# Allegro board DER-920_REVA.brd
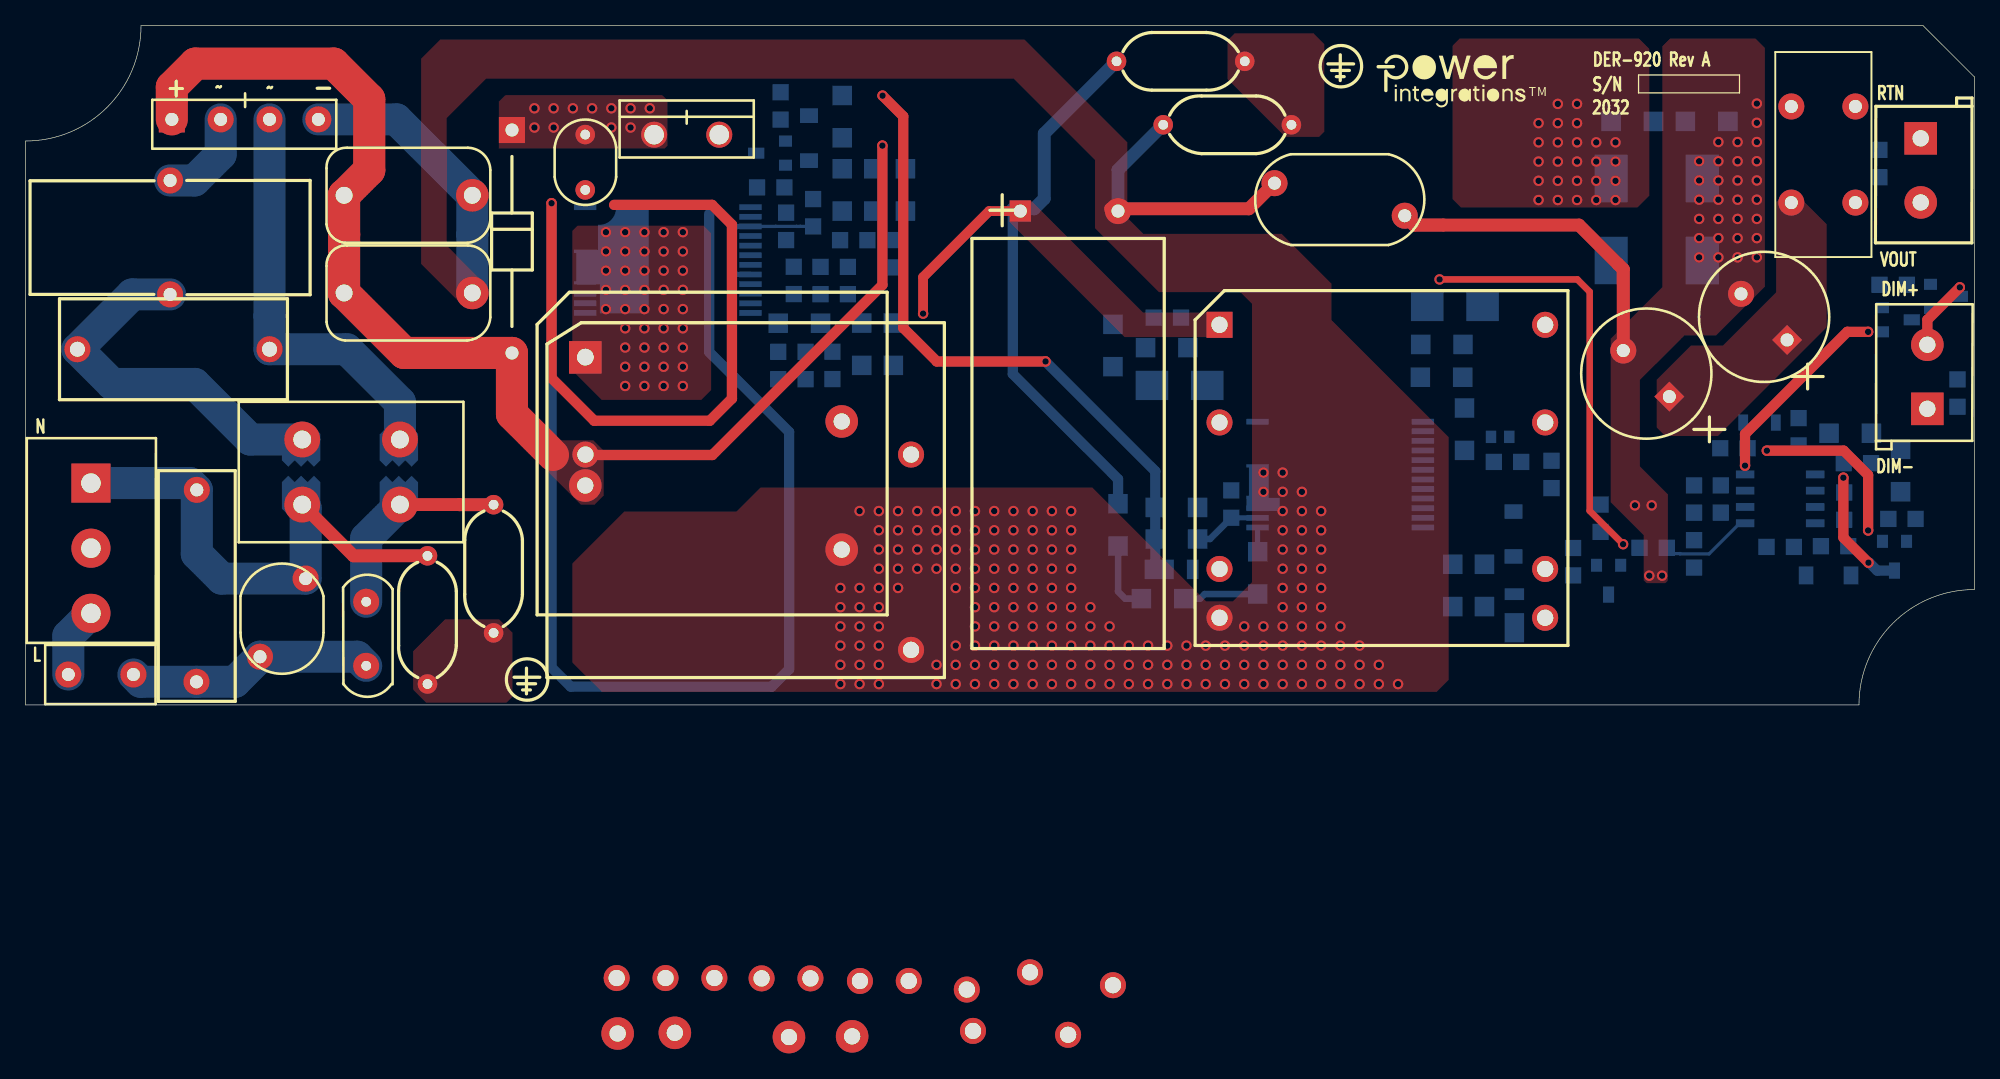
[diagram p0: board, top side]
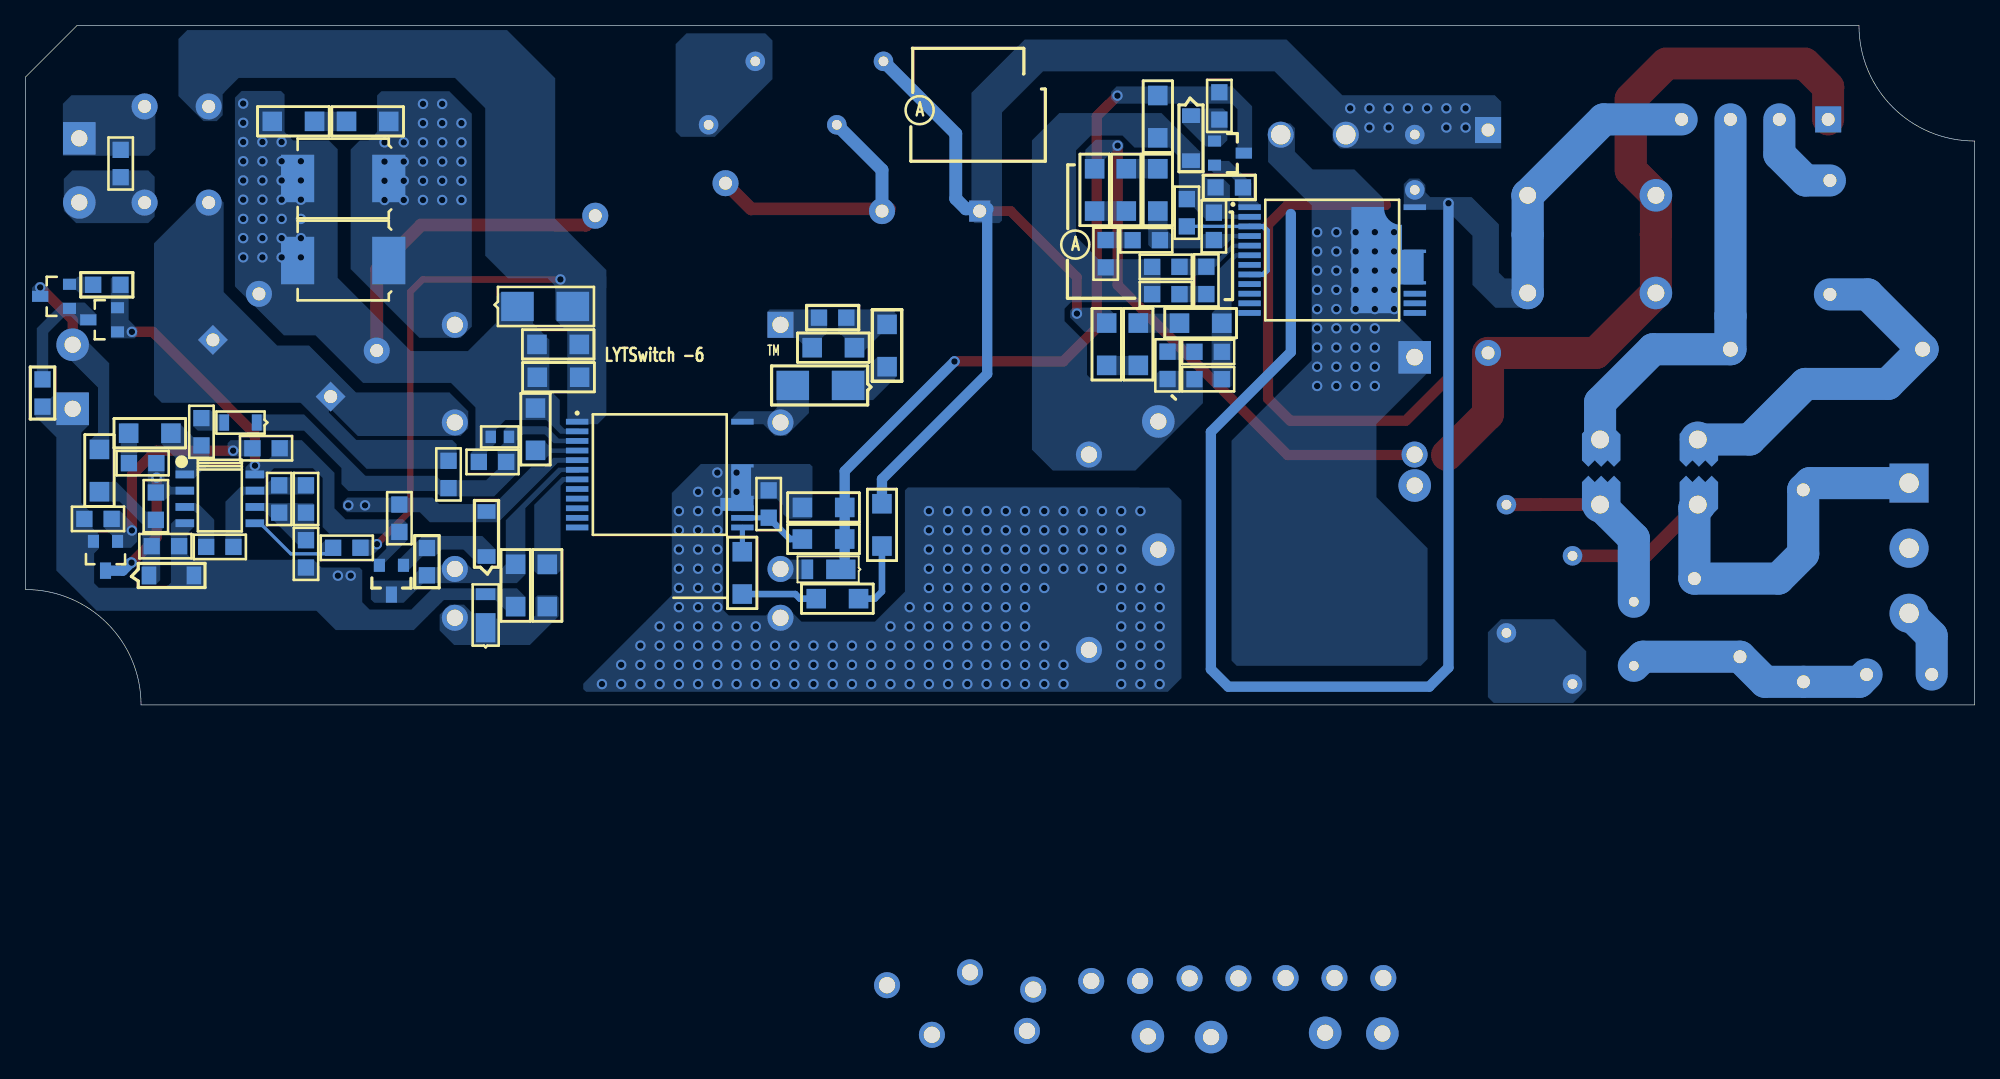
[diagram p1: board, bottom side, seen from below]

Outline 152 x 53 mm; copper layers: TOP, BOTTOM. Coordinates in mm from the lower left corner of the outline.
Outline path: 0,44 0,0 143,0 arc(145.64,6.36) 152,9 152,49 148,53 9,53 arc(6.36,46.64) 0,44

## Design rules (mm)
constraint set DEFAULT: min track width 0.508

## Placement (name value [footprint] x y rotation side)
BR1  UD4KB100-BP  [PIDAXBRIDGED3K]  11.4 45.68 0 top
C1  330 nF  [PI_NP_CAPRAD512X299LS394D040]  24.84 39.76 0 top
C2  330 nF  [PI_NP_CAPRAD512X299LS394D040]  24.84 32.14 0 top
C3  68 nF  [PINPCAPRAD18X6XLS15MMD040]  13.35 1.78 90 top
C4  330 nF  [PINPXCAPRAD710X315590046]  19.02 27.75 180 top
C6  100 nF  [PISMC0805]  144.59 41.17 90 bottom
C7  330 uF  [PIPOLCAPCYLD400LS200040]  128.21 24.06 135 top
C8  330 uF  [PIPOLCAPCYLD400LS200040]  137.39 28.48 135 top
C9  1000 pF  [PISMC0805]  87.99 30.22 0 bottom
C10  220 pf  [PISMC1206]  129.46 45.53 0 bottom
C12  3.3 nF  [PINPYCAPRAD540X290LS400040]  97.41 40.71 0 top
C13  47 uF  [PIPOLCAPCLYD600LS300040]  77.58 38.53 0 top
C14  10 nF  [PI_NP_CAP250X200LS170D030]  43.65 44.5 270 top
C15  330 pF  [PISMC0603]  115.72 20.91 180 bottom
C16  2.2 uF  [PISMC1206]  112.23 23.16 270 bottom
C17  100 nF  [PISMC0805]  61.43 37.34 90 bottom
C18  1 uF  [PISMC0805]  57.05 40.38 0 bottom
C19  470 pF  [PISMC0805]  58.7 25.42 0 bottom
C20  10 uF  [PISMC1206]  63.69 47.55 270 bottom
C21  470 pF  [PISMC0805]  59.32 36.27 90 bottom
C22  100 nF  [PISMC0805]  62 34.18 0 bottom
C23  1 uF  [PISMC0805]  62 32.05 0 bottom
C25  2.2 uF  [PISMC0805]  134.32 20.03 180 bottom
C26  10 uF  [PISMC1206]  88.11 15.41 0 bottom
C27  4.7 uF  [PISMC0805]  94.04 14.61 90 bottom
C28  .22 uF  [PISMC1206]  140.67 21.2 0 bottom
C29  3.3 uF  [PISMC0805]  140.03 12.38 0 bottom
C30  1 nF  [PISMC0805]  132.22 15 90 bottom
C31  10 uF  [PISMC1206]  113.78 10.97 270 bottom
C32  100 nF  [PISMC0805]  122.85 13.5 90 bottom
C33  2200 pF  [PINPCAPRAD9MMXLS10MM030]  36.5 15.62 270 top
C34  2200 pF  [PINPCAPRAD9MMXLS10MM030]  31.34 11.63 270 top
C35  2200 pF  [PINPCAPRAD9MMXLS10MM030]  85.09 50.22 0 top
C36  2200 pF  [PINPCAPRAD9MMXLS10MM030]  98.73 45.26 180 top
D2  1N4006  [PIDV200X110X040DO41]  37.93 43.26 270 top
D3  S1K-E3/61T  [PISMDO214AC12]  87.85 24.93 0 bottom
D4  STTH3R04S  [PISMDO214AB12]  123.67 41.07 0 bottom
D5  LQA03TC600  [PIDVT0220ACREVA]  54.1 44.49 180 top
D7  DFLR1400-7  [PISMDDFLR120012]  88.39 10.58 180 bottom
D9  B340A-13-F  [PISMDO214AC12]  113.64 31.09 180 bottom
D11  DFLU1200-7  [PISMDDFLR120012]  116.12 5.99 270 bottom
D12  STTH3R04S  [PISMDO214AB12]  123.67 34.67 0 bottom
D13  BAS21HT1G  [PISMSOD323]  133.97 22.03 0 bottom
F1  3.15 A  [PI_RST_MICROFUSE]  3.33 2.37 0 top
J1  TERMINAL BLOCK  [PI_TERM_BLOCK_3PIN]  5.09 17.31 180 top
J2  TERMINAL BLOCK  [PI_TERM_BLOCK_2PIN_LS200]  147.82 44.21 180 top
J6  TERMINAL BLOCK  [PI_TERM_BLOCK_2PIN_LS200]  148.33 23.1 0 top
L1  20mH  [PI_IND_4P_690X512LS300X200D055]  21.57 15.63 90 top
L2  2120-V-RC  470uH  [PI_TOROID_2P_350X860_LS330_D038]  11.27 32.03 90 top
L3  1.8 mH  [PI_COIL_16X8_LS8X7P5]  142.72 39.19 90 top
NOREF  -  []  152 0 90 top
NOREF#2  -  []  9 53 0 top
NOREF#3  -  []  105.38 51.18 0 top
NOREF#4  -  []  145.71 6.44 0 top
NOREF#5  -  []  152 9 90 top
NOREF#6  -  []  0 44 0 top
Q1  MMBTA06LT1G  [PISMSOT23123_1]  59.27 42.11 270 bottom
Q3  MMBT3906  [PISMSOT23123_1]  148.58 32.82 90 bottom
Q5  2N7002  [PISMSOT23123_1]  146.71 12.76 0 bottom
Q6  MMBTA06LT1G  [PISMSOT23123_1]  124.41 10.9 0 bottom
R4  590 k  [PISMR0805]  119.01 19.05 270 bottom
R5  240 k  [PISMR1206]  90.65 27.87 180 bottom
R6  20  [PISMR1206]  126.97 45.53 180 bottom
R7  15.8 k  [PISMR0805]  114.52 18.96 0 bottom
R8  3.74 M  [PISMR1206]  67.68 29.79 270 bottom
R9  6.2 M  [PISMR1206]  65.21 26.49 90 bottom
R10  6.2 M  [PISMR1206]  68.62 41.83 270 bottom
R11  6.2 M  [PISMR1206]  66.15 38.53 90 bottom
R12  6.2 M  [PISMR1206]  58.7 29.78 0 bottom
R13  3.74 M  [PISMR1206]  63.69 41.83 270 bottom
R14  18.7 k  [PISMR0805]  144.6 32.78 0 bottom
R15  30.1 k  [PISMR0805]  59.91 34.19 270 bottom
R17  10 k  [PISMR0805]  63.53 36.26 0 bottom
R18  143 k  [PISMR0805]  67.76 36.27 270 bottom
R19  10 k  [PISMR0805]  58.7 27.55 0 bottom
R20  143 k  [PISMR0805]  62.93 27.56 270 bottom
R21  120 k  [PISMR1206]  88.11 12.94 0 bottom
R22  221 k  [PISMR0805]  138.29 22.38 270 bottom
R23  20.0 k  [PISMR1206]  146.24 16.64 90 bottom
R24  0.04  [PISMR1206]  108.81 28.13 0 bottom
R27  10 k  [PISMR0805]  150.68 25.4 270 bottom
R29  10 k  [PISMR0805]  145.29 14.51 0 bottom
R30  47  [PISMR1206]  111.31 7.67 90 bottom
R31  0.068  [PISMR1206]  108.79 25.57 0 bottom
R32  10 k  [PISMR0805]  141.81 18.86 0 bottom
R34  261 k  [PISMR0805]  130.13 17.13 270 bottom
R37  1.00 k  [PISMR0805]  128.02 12.26 180 bottom
R38  1.00 k  [PISMR0805]  130.13 12.85 270 bottom
R39  1.00 k  [PISMR0805]  137.92 12.33 180 bottom
R41  1.00 k  [PISMR0805]  141.84 16.57 270 bottom
R45  1.33 M  [PISMR1206]  85.21 15.7 270 bottom
R46  1.33 M  [PISMR1206]  87.03 8.29 0 bottom
R47  1.33 M  [PISMR1206]  96.1 8.65 90 bottom
R50  100 k  [PISMR0805]  58.89 47.8 270 bottom
R53  30 k  [PISMR0805]  120.7 10.11 90 bottom
R54  20  [PISMR1206]  84.81 26.39 90 bottom
RT1  2.5  [PI_RAD150X300LS200D030]  26.56 3.05 90 top
RV1  300 Vac  [PIDISC350X225LS240X140040]  18.28 3.76 90 top
T2  BEF25  [PI_BOBBIN_EF25_8P_H]  43.65 27.12 0 top
T3  PQ26/20  [PI_BOBBIN_BPQ26_20_12P]  93.12 29.66 0 top
T4  PQ26/25  [PIBOBBINPQ262512P]  43.66 27.15 0 top
U2  PFS7624C  [PI_IC_INSOP24B]  50.09 34.71 180 bottom
U3  LM431BIM3/NOPB  [PISMSOT23123]  144.83 30.99 90 bottom
U4  LYT6078C  [PI_IC_INSOP_24D]  108.98 22.1 180 bottom
U5  TSX712IDT  [PISMSO8]  139.58 17.99 270 bottom
VR1  MMSZ4700T1G  [PI_SM_SOD-123_12]  61.1 45.97 270 bottom
VR2  MMSZ5242B-7-F  [PI_SM_SOD-123_12]  142.38 10.1 180 bottom
VR3  MMSZ4700T1G  [PI_SM_SOD-123_12]  116.05 11.58 90 bottom

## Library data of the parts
BR1 = DISCRETE BRIDGE_+~~-: alternate symbols: (pidaxbridgeD3K_horz)
C1 C2 = CAP NP: alternate symbols: (pi_np_caprad512x299ls394d040_h)
C3 = CAP NP: alternate symbols: (piNPcapRAD18x6xLS15mmd040H)
C4 C6 C9 C10 C14-C19 C21-C23 C25 C27-C36 = CAP NP
C7 C8 = CAP POL: alternate symbols: (pipolcapcyld400ls200040800h)
C12 = CAP NP: alternate symbols: (pinpycaprad540x290ls400040h)
C13 = CAP POL: alternate symbols: (pipolcapd630ls3000401120lhoriz)
C20 C26 = CAP NP: alternate symbols: (pismc1206_1)
D2 = DIODE: alternate symbols: (pidax475x125040do41,pidv200x110x040do41wbead,pidax390x125040do41)
D3-D5 D7 D11 D12 = DIODE
D9 = DIODE SCHOTTKY
D13 = DIODE: alternate symbols: (pismsod323_1)
F1 = FUSE: alternate symbols: (pirstmicrofusehoz)
J1 = CON3
J2 J6 = CON2
L1 = INDUCTOR_4P_revD: alternate symbols: (pi_4p_700x400d055_horiz)
L2 = INDUCTOR: alternate symbols: (pi_2p_700x400d055_horiz)
L3 = TORRID 4P_14_23
Q1 Q6 = NPN_BEC
Q3 = PNP_BEC
Q5 = FET_N_GSD
R4-R15 R17-R24 R27 R29-R32 R37-R39 R41 R45-R47 R50 R53 R54 = R
R34 = R: alternate symbols: (pismr0805_1)
RT1 = THERMISTOR: alternate symbols: (pirad400x300ls200040_h)
RV1 = VARISTOR
T2 = BEF25_8P/GENERIC
T3 = BPQ26/20_12P/GENERIC
T4 = BPQ26/25_12P/GENERIC
U2 = HIPERPFS-4-inSOP24B
U3 = TL431/SOT-23_CAR
U4 = LYT6
U5 = TSX712IDT
VR1-VR3 = DIODE_ZENER

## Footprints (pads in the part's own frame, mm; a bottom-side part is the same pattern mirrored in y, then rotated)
PI_BOBBIN_BPQ26_20_12P
  rect 2.032x2.032 hole 1.27: 1(0,0)
  round 2.032 hole 1.27: 2(-14.783,-50.521) 3(0,-7.62) 4(-19.228,-55.093) 5(0,-19.05) 6(0,-22.86) 7(25.4,-22.86) 8(25.4,-19.05) 9(-19.71,-51.867) 10(25.4,-7.62) 11(-11.811,-55.397) 12(25.4,0)
PI_BOBBIN_EF25_8P_H
  rect 2.54x2.54 hole 1.27: 1(0,0)
  round 2.54 hole 1.27: 2(6.985,-52.702) 3(0,-10) 4(2.524,-52.756) 5(20,-15.001) 6(20.813,-52.977) 7(20,-5.001) 8(15.885,-53.035)
PI_COIL_16X8_LS8X7P5
  round 2.032 hole 1.016: 1(0,5) 2(7.5,5) 3(7.5,0) 4(0,0)
PI_IC_INSOP24B
  rect 1.75x0.45 smd: 1(-6.445,4.125) 2(-6.445,3.375) 3(-6.445,2.625) 4(-6.445,1.875) 5(-6.445,1.125) 6(-6.445,0.375) 7(-6.445,-0.375) 8(-6.445,-1.125) 9(-6.445,-1.875) 10(-6.445,-2.625) 11(-6.445,-3.375) 12(-6.445,-4.125) 13(6.445,-4.125) 14(6.445,-3.375) 15(6.445,-2.625) 24(6.445,4.125)
  custom 0.438x0.438 smd: 16(6.445,-0.545)
PI_IC_INSOP_24D
  rect 1.75x0.45 smd: 1(0,0) 2(0,-0.75) 3(0,-1.5) 4(0,-2.25) 5(0,-3) 6(0,-3.75) 7(0,-4.5) 8(0,-5.25) 9(0,-6) 10(0,-6.75) 11(0,-7.5) 12(0,-8.25) 13(12.89,-8.25) 14(12.89,-7.5) 15(12.89,-6.75) 24(12.89,0)
  custom 0.438x0.438 smd: 16(12.89,-4.67)
PI_IND_4P_690X512LS300X200D055
  round 2.794 hole 1.397: 1(0,0) 2(5.08,0) 3(5.08,-7.62) 4(0,-7.62)
PI_NP_CAP250X200LS170D030
  round 1.524 hole 0.762: 1(0,0) 2(4.318,0)
PI_NP_CAPRAD512X299LS394D040
  round 2.54 hole 1.321: 1(0,0) 2(10,0)
PI_RAD150X300LS200D030
  round 2.032 hole 0.762: 1(0,0) 2(5,0)
PI_RST_MICROFUSE
  round 2.032 hole 1.016: 1(0,0) 2(5.08,0)
PI_SM_SOD-123_12
  rect 1.143x1.397 smd: 1(0,0) 2(3.505,0)
PI_TERM_BLOCK_2PIN_LS200
  rect 2.54x2.54 hole 1.27: 1(0,0)
  round 2.54 hole 1.27: 2(0,5.001)
PI_TERM_BLOCK_3PIN
  rect 3.048x3.048 hole 1.524: 1(0,0)
  round 3.048 hole 1.524: 2(0,5.08) 3(0,10.16)
PI_TOROID_2P_350X860_LS330_D038
  round 2.032 hole 1.016: 1(0,0) 2(8.89,0)
PIBOBBINPQ262512P
  rect 2.032x2.032 hole 1.27: 1(0,0)
  round 2.032 hole 1.27: 2(41.148,-49.022) 3(0,-7.62) 4(2.438,-48.463) 5(6.248,-48.463) 6(10.058,-48.463) 7(25.4,-22.86) 8(17.551,-48.489) 9(13.741,-48.489) 10(25.4,-7.62) 11(25.222,-48.692) 12(21.412,-48.692)
PIDAXBRIDGED3K
  rect 2.032x2.032 hole 1.016: 1(0,0)
  round 2.032 hole 1.016: 2(3.81,0) 3(7.62,0) 4(11.43,0)
PIDISC350X225LS240X140040
  round 2.032 hole 1.016: 1(0,0) 2(6.096,-3.556)
PIDV200X110X040DO41
  rect 2.032x2.032 hole 1.016: 1(-1.6,0)
  round 2.032 hole 1.016: 2(15.795,0)
PIDVT0220ACREVA
  round 2.032 hole 1.524: 1(5.08,0) 2(0,0)
PINPCAPRAD9MMXLS10MM030
  round 1.524 hole 0.762: 1(0,0) 2(10,0)
PINPCAPRAD18X6XLS15MMD040
  round 2.032 hole 1.016: 1(0.025,0.025) 2(15,0)
PINPXCAPRAD710X315590046
  round 2.032 hole 1.168: 1(0,0) 2(14.986,0)
PINPYCAPRAD540X290LS400040
  round 2.032 hole 1.016: 1(0,0) 2(10.16,-2.54)
PIPOLCAPCLYD600LS300040
  rect 1.651x1.651 hole 1.016: 1(0,0)
  round 2.032 hole 1.016: 2(7.62,0)
PIPOLCAPCYLD400LS200040
  rect 1.651x1.651 hole 1.016: 1(0,0)
  round 2.032 hole 1.016: 2(5.08,0)
PISMC0603
  rect 0.813x0.965 smd: 1(0,0) 2(1.422,0)
PISMC0805
  rect 1.27x1.27 smd: 1(0,0) 2(2.134,0)
PISMC1206
  rect 1.524x1.524 smd: 1(0,0) 2(3.302,0)
PISMDDFLR120012
  rect 2.286x1.524 smd: 1(-0.025,0)
  rect 0.914x1.524 smd: 2(-2.642,0)
PISMDO214AB12
  rect 2.591x3.708 smd: 1(0,0) 2(7.112,0)
PISMDO214AC12
  rect 2.54x2.286 smd: 1(0,0) 2(4.318,0)
PISMR0805
  rect 1.27x1.27 smd: 1(0,0) 2(2.134,0)
PISMR1206
  rect 1.524x1.524 smd: 1(0,0) 2(3.302,0)
PISMSO8
  rect 0.61x1.448 smd: 1(0,0) 2(1.27,0) 3(2.54,0) 4(3.81,0) 5(3.81,5.461) 6(2.54,5.461) 7(1.27,5.461) 8(0,5.461)
PISMSOD323
  rect 0.762x1.27 smd: 1(0,0) 2(2.54,0)
PISMSOT23123
  rect 0.864x1.016 smd: 1(-1.88,0) 3(0,0)
  rect 0.864x1.27 smd: 2(-0.94,2.286)
PISMSOT23123_1
  rect 0.864x1.016 smd: 1(-1.88,0) 2(0,0)
  rect 0.864x1.27 smd: 3(-0.94,2.286)

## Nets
GND_EARTH: C33.2 C34.2 C35.2 C36.1
DIM+: J6.2 Q3.3 R23.2
DIM-: C7.2 C8.2 C10.2 C12.2 C15.1 C16.1 C29.1 C31.2 C32.2 D4.2 D9.1 D11.2 D12.2 J6.1 Q5.2(S) R7.2 R24.2 R27.2 R29.2 R31.2 R38.2 U4.2 U4.5 U5.4 VR2.2 VR3.2
FB_PIN: C15.2 D13.1 R4.2 R7.1 U4.3
NC8: U4.8
NC9: U4.9
NC10: U4.10
NC11: U4.11
NC12: U4.12
NC15: U4.15
RS+: D9.2 L3.2 R24.1 R31.1 R37.2 U4.1
SB_A: D11.1 R30.1 T3.7
SB_B: C31.1 Q6.3 R53.1 T3.8 U4.6
SOURCE: BR1.4 C1.2 C2.2 C12.1 C13.2 C14.2 C26.2 C27.2 C36.2 T2.5 T3.6 T4.7 U2.24 U4.16
VDC AUX: C20.1 C26.1 D7.1 Q1.3 R21.1 R50.1
VRECT: BR1.1 C1.1 C2.1 D2.2 R10.1 T2.3 T4.3
N11474046: F1.1 J1.3
N11474062: C3.1 F1.2 RT1.1 RV1.1
N11474110: C33.1 L1.4 RT1.2
N11474114: BR1.3(AC2) C4.1 L1.3
N11474138: BR1.2 L2.2
N11474236: C3.2 C34.1 J1.1 L1.1 RV1.2
N11474420: C4.2 L1.2 L2.1
N11475153: C9.2 C13.1 C14.1 C35.1 D2.1 D5.1 R5.1 R8.1 R45.1 T3.1
N11476179: D5.2 T2.1 T4.1 U2.16
N11479125: C18.1 Q1.2(EMITTER) U2.1(VCC)
N11479237: C17.2 C18.2 C19.2 C20.2 C21.2 C22.2 C23.2 R18.2 R20.2 T2.7 T4.10 U2.2 U2.12 VR1.2
N11479555: C22.1 R15.1 U2.5
N11479611: C23.1 R15.2
N11480864: R10.2 R11.1
N11480868: R11.2 R13.1
N11480902: C21.1 R13.2 R17.1 U2.4
N11482311: R8.2 R9.1
N11482333: R9.2 R12.2
N11482355: C19.1 R12.1 R19.1 U2.6
N11498787: C7.1 C8.1 L3.1 R4.1 T3.10
N11498823: C6.1 J2.2 L3.4
N11498915: C6.2 J2.1 L3.3
N11498945: C9.1 R5.2 R54.2
N11499167: D4.1 D12.1 R6.2 T3.12
N11499175: C10.1 R6.1
N11499225: D3.2 T3.3 U4.24
N11499609: R30.2 U4.7
N11499647: R47.2 U4.13(VPIN)
N11499655: C16.2 U4.4
N11499799: C27.1 R21.2 U4.14
N11939314: R19.2 R20.1
N11966145: D7.2 T3.5
N11977822: C17.1 U2.3 U2.8
N11995900: Q1.1 R50.2 VR1.1
N12000412: R17.2 R18.1
N12016680: R45.2 R46.1
N12017060: R46.2 R47.1
N12033400: C25.2 C32.1 Q6.2(EMITTER) R14.1 U3.1 U3.3(VREF) U5.8
N12033444: Q3.2(EMITTER) R14.2
N12033508: Q3.1 R27.1 U3.2
N12033698: R39.1 U5.3
N12033710: C29.2 R23.1 R41.2 VR2.1
N12033758: D13.2 R22.1
N12033762: C28.1 R22.2 U5.1
N12033774: Q5.3 R32.1 R41.1 U5.2
N12033856: C25.1 Q5.1 R29.1
N12033928: C28.2 R32.2
N12034090: C30.1 R34.2 R38.1 U5.6
N12034098: C30.2 R34.1 R39.2 U5.7(OUT)
N12052159: Q6.1 R53.2 VR3.1
N12053445: D3.1 R54.1
N12080403: R37.1 U5.5

Pads without a net: J1 2; T2 2 4 6 8; T3 2 4 9 11; T4 2 4 5 6 8 9 11 12; U2 7 9 10 11 13 14 15

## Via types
v1: diameter 0.813, hole 0.508, TOP to BOTTOM, 310 vias

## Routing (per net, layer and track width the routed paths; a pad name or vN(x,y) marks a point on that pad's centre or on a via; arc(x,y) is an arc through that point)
DIM+: length 5.5
  TOP w0.8: J6.2 148.33,30.05 v1(150.87,32.58)
DIM-: length 25.4
  TOP w1: 110.59,37.44 121.16,37.44 124.21,34.39
  TOP w1.016: C12.2 108.3,37.44 110.59,37.44 ; 124.21,34.39 124.62,33.98 C7.2 124.79,27.82
  vias: v1(125.53,15.57) v1(126.64,10.08) v1(126.83,15.57) v1(127.64,10.08) v1(130.53,42.42) v1(130.53,40.92) v1(130.53,39.42) v1(130.53,37.92) v1(130.53,36.42) v1(130.53,34.92) v1(132.03,43.92) v1(132.03,42.42) v1(132.03,40.92) v1(132.03,39.42) v1(132.03,37.92) v1(132.03,36.42) v1(132.03,34.92) v1(133.53,43.92) v1(133.53,42.42) v1(133.53,40.92) v1(133.53,39.42) v1(133.53,37.92) v1(133.53,36.42) v1(133.53,34.92) v1(135.03,46.92) v1(135.03,45.42) v1(135.03,43.92) v1(135.03,42.42) v1(135.03,40.92) v1(135.03,39.42) v1(135.03,37.92) v1(135.03,36.42) v1(135.03,34.92)
RS+: length 32.9
  TOP w0.508: v1(124.6,12.54) 122,15.14 122,32.23 121.03,33.2 v1(110.29,33.2)
SOURCE: length 191.1
  TOP w0.8: v1(41.02,39.14) 41.02,25.5 44.35,22.17 53.37,22.17 55.09,23.9 55.09,37.47 53.54,39.01 45.9,39.01
  TOP w1: C12.1 95.41,38.71 84.62,38.71
  BOTTOM w0.8: v1(41.02,39.14) 41.02,2.92 42.52,1.42 58.19,1.42 59.55,2.78 59.55,21.3 53.31,27.53 53.31,38.3
  BOTTOM w1: C13.2 85.2,41.74 C36.2
  BOTTOM w2.5: C2.2 34.84,36.71 C1.2 28.92,45.68 BR1.4
  vias: v1(63.55,9.13) v1(63.55,7.63) v1(63.55,6.13) v1(63.55,4.63) v1(63.55,3.13) v1(63.55,1.63) v1(65.05,15.13) v1(65.05,9.13) v1(65.05,7.63) v1(65.05,6.13) v1(65.05,4.63) v1(65.05,3.13) v1(65.05,1.63) v1(66.55,15.13) v1(66.55,13.63) v1(66.55,12.13) v1(66.55,10.63) v1(66.55,9.13) v1(66.55,7.63) v1(66.55,6.13) v1(66.55,4.63) v1(66.55,3.13) v1(66.55,1.63) v1(68.05,15.13) v1(68.05,13.63) v1(68.05,12.13) v1(68.05,10.63) v1(68.05,9.13) v1(69.55,15.13) v1(69.55,13.63) v1(69.55,12.13) v1(69.55,10.63) v1(71.05,15.13) v1(71.05,13.63) v1(71.05,12.13) v1(71.05,10.63) v1(71.05,3.13) v1(71.05,1.63) v1(72.55,15.13) v1(72.55,13.63) v1(72.55,12.13) v1(72.55,10.63) v1(72.55,9.13) v1(72.55,4.63) v1(72.55,3.13) v1(72.55,1.63) v1(74.05,15.13) v1(74.05,13.63) v1(74.05,12.13) v1(74.05,10.63) v1(74.05,9.13) v1(74.05,7.63) v1(74.05,6.13) v1(74.05,4.63) v1(74.05,3.13) v1(74.05,1.63) v1(75.55,15.13) v1(75.55,13.63) v1(75.55,12.13) v1(75.55,10.63) v1(75.55,9.13) v1(75.55,7.63) v1(75.55,6.13) v1(75.55,4.63) v1(75.55,3.13) v1(75.55,1.63) v1(77.05,15.13) v1(77.05,13.63) v1(77.05,12.13) v1(77.05,10.63) v1(77.05,9.13) v1(77.05,7.63) v1(77.05,6.13) v1(77.05,4.63) v1(77.05,3.13) v1(77.05,1.63) v1(78.55,15.13) v1(78.55,13.63) v1(78.55,12.13) v1(78.55,10.63) v1(78.55,9.13) v1(78.55,7.63) v1(78.55,6.13) v1(78.55,4.63) v1(78.55,3.13) v1(78.55,1.63) v1(80.05,15.13) v1(80.05,13.63) v1(80.05,12.13) v1(80.05,10.63) v1(80.05,9.13) v1(80.05,7.63) v1(80.05,6.13) v1(80.05,4.63) v1(80.05,3.13) v1(80.05,1.63) v1(81.55,15.13) v1(81.55,13.63) v1(81.55,12.13) v1(81.55,10.63) v1(81.55,9.13) v1(81.55,7.63) v1(81.55,6.13) v1(81.55,4.63) v1(81.55,3.13) v1(81.55,1.63) v1(83.05,7.63) v1(83.05,6.13) v1(83.05,4.63) v1(83.05,3.13) v1(83.05,1.63) v1(84.55,6.13) v1(84.55,4.63) v1(84.55,3.13) v1(84.55,1.63) v1(86.05,4.63) v1(86.05,3.13) v1(86.05,1.63) v1(87.55,4.63) v1(87.55,3.13) v1(87.55,1.63) v1(89.05,4.63) v1(89.05,3.13) v1(89.05,1.63) v1(90.55,4.63) v1(90.55,3.13) v1(90.55,1.63) v1(92.05,4.63) v1(92.05,3.13) v1(92.05,1.63) v1(93.55,4.63) v1(93.55,3.13) v1(93.55,1.63) v1(95.05,6.13) v1(95.05,4.63) v1(95.05,3.13) v1(95.05,1.63) v1(96.55,18.13) v1(96.55,16.63) v1(96.55,6.13) v1(96.55,4.63) v1(96.55,3.13) v1(96.55,1.63) v1(98.05,18.13) v1(98.05,16.63) v1(98.05,15.13) v1(98.05,13.63) v1(98.05,12.13) v1(98.05,10.63) v1(98.05,9.13) v1(98.05,7.63) v1(98.05,6.13) v1(98.05,4.63) v1(98.05,3.13) v1(98.05,1.63) v1(99.55,16.63) v1(99.55,15.13) v1(99.55,13.63) v1(99.55,12.13) v1(99.55,10.63) v1(99.55,9.13) v1(99.55,7.63) v1(99.55,6.13) v1(99.55,4.63) v1(99.55,3.13) v1(99.55,1.63) v1(101.05,15.13) v1(101.05,13.63) v1(101.05,12.13) v1(101.05,10.63) v1(101.05,9.13) v1(101.05,7.63) v1(101.05,6.13) v1(101.05,4.63) v1(101.05,3.13) v1(101.05,1.63) v1(102.55,6.13) v1(102.55,4.63) v1(102.55,3.13) v1(102.55,1.63) v1(104.05,4.63) v1(104.05,3.13) v1(104.05,1.63) v1(105.55,3.13) v1(105.55,1.63) v1(107.05,1.63)
VDC AUX: length 50.9
  TOP w0.8: v1(66.84,47.54) 68.45,45.92 68.45,29.41 71.07,26.8 v1(79.55,26.8)
  BOTTOM w0.8: D7.1 88.11,10.88 R21.1 88.11,15.41 C26.1 88.11,18.24 v1(79.55,26.8)
VRECT: length 99.6
  TOP w0.8: 43.65,19.5 53.56,19.5 66.83,32.77 v1(66.83,43.64)
  TOP w2.5: 41.13,19.5 37.93,22.7 D2.2 29.52,27.46 C2.1 24.84,36.71 C1.1 26.8,41.72 26.8,47.26 24.03,50.04 13.24,50.04 11.4,48.2 BR1.1
N11474046: length 5.5
  BOTTOM w2.5: F1.1 3.33,5.38 J1.3
N11474062: length 19.5
  BOTTOM w2.5: F1.2 8.98,1.8 C3.1 16.32,1.8 RV1.1 25.85,3.76 RT1.1
N11474110: length 16
  TOP w1: L1.4 33.81,15.63 33.82,15.62 C33.1
  BOTTOM w2.5: L1.4 26.56,13 RT1.2
N11474114: length 32.7
  BOTTOM w2.5: BR1.3 19.02,30.35 19.02,30.35 C4.1 25.05,27.75 29.19,23.61 L1.3
N11474138: length 7.5
  BOTTOM w2.5: L2.2 13.17,40.92 15.21,42.96 BR1.2
N11474236: length 40.1
  TOP w1: L1.1 25.57,11.63 C34.1
  BOTTOM w2.5: J1.1 12.82,17.31 C3.2 13.35,11.79 15.29,9.86 RV1.2 21.84,15.37 L1.1
N11474420: length 29.5
  BOTTOM w2.5: L1.2 17.52,20.71 13.18,25.04 6.75,25.04 C4.2 8.32,32.03 L2.1
N11475153: length 54.8
  TOP w0.762: C13.1 75.16,38.53 70,33.38 v1(70,30.53)
  BOTTOM w0.8: 77,38.71 77,25.82 85.21,17.61 R45.1
  BOTTOM w1: C35.1 79.45,44.58 79.45,39.5 78.66,38.71 77,38.71
  vias: v1(39.68,46.55) v1(39.68,45.05) v1(41.18,46.55) v1(41.18,45.05) v1(42.68,46.55) v1(44.18,46.55) v1(45.68,46.55) v1(45.68,45.05) v1(47.18,46.55) v1(47.18,45.05) v1(48.68,46.55)
N11476179:
  vias: v1(45.26,36.88) v1(45.26,35.38) v1(45.26,33.88) v1(45.26,32.38) v1(45.26,30.88) v1(46.76,36.88) v1(46.76,35.38) v1(46.76,33.88) v1(46.76,32.38) v1(46.76,30.88) v1(46.76,29.38) v1(46.76,27.88) v1(46.76,26.38) v1(46.76,24.88) v1(48.26,36.88) v1(48.26,35.38) v1(48.26,33.88) v1(48.26,32.38) v1(48.26,30.88) v1(48.26,29.38) v1(48.26,27.88) v1(48.26,26.38) v1(48.26,24.88) v1(49.76,36.88) v1(49.76,35.38) v1(49.76,33.88) v1(49.76,32.38) v1(49.76,30.88) v1(49.76,29.38) v1(49.76,27.88) v1(49.76,26.38) v1(49.76,24.88) v1(51.26,36.88) v1(51.26,35.38) v1(51.26,33.88) v1(51.26,32.38) v1(51.26,30.88) v1(51.26,29.38) v1(51.26,27.88) v1(51.26,26.38) v1(51.26,24.88)
N11499167:
  vias: v1(118.01,45.39) v1(118.01,43.89) v1(118.01,42.39) v1(118.01,40.89) v1(118.01,39.39) v1(119.51,46.89) v1(119.51,45.39) v1(119.51,43.89) v1(119.51,42.39) v1(119.51,40.89) v1(119.51,39.39) v1(121.01,46.89) v1(121.01,45.39) v1(121.01,43.89) v1(121.01,42.39) v1(121.01,40.89) v1(121.01,39.39) v1(122.51,43.89) v1(122.51,42.39) v1(122.51,40.89) v1(122.51,39.39) v1(124.01,43.89) v1(124.01,42.39) v1(124.01,40.89) v1(124.01,39.39)
N11499647: length 1.9
  BOTTOM w0.4: U4.13 96.09,11.96 R47.2
N11499799: length 5.4
  BOTTOM w0.4: U4.14 94.05,14.6 C27.1
  BOTTOM w0.508: C27.1 92.38,12.94 R21.2
N11977822: length 11
  BOTTOM w0.254: C17.1 60.41,37.34 60.41,37.33 60.14,37.33 60.13,37.34 58.51,37.34 58.5,37.33 U2.3
  BOTTOM w0.4: U2.3 55.47,37.33 55.15,37.02 55.15,33.9 55.47,33.58 U2.8
N12016680: length 5.6
  BOTTOM w0.508: R46.1 85.76,8.29 85.21,8.85 R45.2
N12017060: length 5.9
  BOTTOM w0.508: R46.2 91.61,8.29 91.96,8.65 R47.1
N12033400: length 15.4
  TOP w0.8: v1(134.11,18.67) 134.11,21.13 142.09,29.11 v1(143.71,29.11)
N12033774: length 9.7
  TOP w0.8: v1(141.78,17.73) 141.78,13.06 v1(143.74,11.1)
  BOTTOM w0.8: v1(143.74,11.1) 143.8,11.1 144.42,10.47 Q5.3
N12033856: length 13
  TOP w0.8: v1(143.71,13.61) 143.71,17.93 141.81,19.84 v1(135.81,19.84)
N12080403: length 7.1
  BOTTOM w0.254: U5.5 133.7,14.18 131.31,11.79 129.07,11.79 129.04,11.81 129.03,11.8 128.02,11.8

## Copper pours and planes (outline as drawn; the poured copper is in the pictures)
GND_EARTH on TOP: 36.93,6.68 32.72,6.68 30.23,4.19 30.23,1.19 31.24,0.18 37.52,0.18 37.97,0.64 37.97,5.64
GND_EARTH on TOP: 94.31,52.4 93.75,51.84 93.75,48.82 98.25,44.32 100.89,44.32 101.3,44.73 101.3,51.56 100.46,52.4
GND_EARTH on BOTTOM: 98.25,44.32 100.89,44.32 101.3,44.73 101.3,51.56 100.46,52.4 94.31,52.4 93.75,51.84 93.75,48.82
GND_EARTH on BOTTOM: 30.28,4.19 30.28,1.17 31.29,0.15 37.49,0.15 37.95,0.61 37.95,5.66 36.93,6.68 32.77,6.68
DIM+ on BOTTOM: 146.35,21.26 146.35,24.77 149.2,27.61 149.2,28.55 148.67,29.08 147.9,29.08 145.48,26.66 145.48,19.18 147,19.18 147.01,19.19 147.01,20.6
DIM+ on BOTTOM: 150.67,32.99 151.05,32.99 151.5,32.55 151.5,31.45 151.5,31.44 150.23,31.44 150.23,32.55
DIM- on TOP: 128.27,51.99 134.92,51.99 135.66,51.26 135.66,32.64 131.85,28.83 129.39,28.83 125.91,25.35 125.91,18.62 128.09,16.43 128.09,9.7 127.89,9.5 126.44,9.5 126.21,9.73 126.21,13.23 123.64,15.81 123.64,28.57 127.66,32.59 127.66,51.38
DIM- on BOTTOM: 108.79,21.54 109.98,21.54 110.34,21.89 110.34,23.8 111.15,24.61 111.15,28.5 112.42,29.77 112.42,31.98 112.64,32.19 114.94,32.19 115.27,31.86 115.27,29.84 117.5,27.61 121.95,27.61 127.66,33.32 127.66,43.36 128.35,44.04 131.14,44.04 131.8,44.7 131.8,47.62 132.08,47.9 135.15,47.9 135.67,47.38 135.67,32.65 131.85,28.83 129.39,28.83 125.68,25.12 118.82,25.12 116.92,23.22 116.92,20.02 117.27,19.66 117.27,19.66 117.27,18.33 116.02,18.33 116.02,19.72 115.31,20.43 115.31,21.49 114.58,22.23 111.38,22.23 110.31,21.16 108.76,21.16 108.71,21.21 108.71,21.46
DIM- on BOTTOM: 113.02,8.44 113.02,6.91 114.54,6.91 114.54,7.37 115.35,8.18 119.38,8.18 121.72,5.84 127.81,5.84 129.31,7.34 146.46,7.34 149.61,10.49 149.61,20.88 151.33,22.61 151.33,23.9 150.07,23.9 149.74,24.23 149.74,24.25 149.61,24.38 147.05,24.38 147.05,21.84 147.65,21.25 147.65,15.75 146.78,14.88 146.78,13.79 146.28,13.29 146.28,12.2 146.66,11.82 146.66,9.5 146.3,9.14 141.06,9.14 140.67,9.54 140.67,14.13 140.32,14.48 138.86,14.48 138.86,13.89 139.39,13.36 139.39,11.74 138.98,11.33 129.54,11.33 128.93,10.72 125.96,10.72 125.74,10.5 125.74,8.01 125.17,7.44 121.92,7.44 120.29,9.07 120.29,9.07 120.26,9.1 113.68,9.1
DIM- on BOTTOM: 108.86,19.28 110.85,19.28 111.58,18.54 112.57,18.54 115.44,15.67 119.75,15.67 120.26,16.18 126.9,16.18 127.27,15.81 127.27,15.38 126.92,15.04 121.26,15.04 120.47,14.25 115.14,14.25 110.49,18.9 108.86,18.9 108.76,19 108.76,19.18
FB_PIN on BOTTOM: 108.79,20.78 110.41,20.78 111.38,21.74 114.4,21.74 114.71,21.43 114.71,20.42 115.19,19.95 115.19,18.39 115.62,17.96 115.65,17.96 116.08,17.53 119.64,17.53 119.99,17.88 125.5,17.88 130.29,22.67 134.35,22.67 134.35,21.4 130.29,21.4 127.37,18.48 127.37,17.23 126.83,16.69 120.07,16.69 119.65,16.28 115.45,16.28 113.7,18.03 113.7,20.62 113.21,21.11 111.51,21.11 110.82,20.42 108.76,20.42 108.71,20.47 108.71,20.7
RS+ on BOTTOM: 109.75,22 109.75,29.13 110.69,30.07 110.69,33.55 110.59,33.66 106.93,33.66 106.71,33.43 106.71,22.58 107.39,21.89 109.65,21.89
RS+ on BOTTOM: 116.15,46.56 118.52,48.92 135.38,48.92 136.5,47.8 136.5,47.78 136.63,47.64 136.63,46.01 137.09,45.55 138.12,45.55 140.08,47.51 140.08,51.96 139.39,52.65 114.45,52.65 110.69,48.9 110.69,37.92 106.71,33.93 106.71,32.51 110.54,32.51 110.69,32.66 110.69,32.69 111.29,33.29 114.39,33.29 116.15,35.05
RS+ on BOTTOM: 124.97,11.63 126.51,11.63 126.51,12.89 126.51,12.89 124.47,12.89 124.23,12.65 124.23,12.37
SB_A on BOTTOM: 117.81,7.82 118.92,7.82 119.71,7.04 119.71,5.82 118.57,4.67 112.67,4.67 110.41,6.93 110.41,8.38 110.59,8.56 112.06,8.56 112.24,8.38 112.24,6.99 112.8,6.43 114.96,6.43 115.36,6.82 115.36,7.16 117.14,7.16
SB_B on BOTTOM: 108.84,18.52 110.44,18.52 114.55,14.41 114.55,10.97 114.96,10.57 117.14,10.57 118.1,11.52 118.96,11.52 119.74,10.74 121.11,10.74 122.15,9.7 124.87,9.7 125.07,9.5 125.07,8.23 124.81,7.97 122.51,7.97 120.98,9.5 113.69,9.5 113.02,10.17 113.02,15.35 110.21,18.16 108.84,18.16 108.76,18.24 108.76,18.44
SOURCE on BOTTOM (solid shape): 97.82,15.14 95.22,15.14 95.22,16.15 97.82,16.15
SOURCE on TOP: 83.41,42.52 77.08,48.86 35.9,48.86 32.84,45.8 32.84,35.84 35.92,32.77 35.92,31.93 35.13,31.14 34.11,31.14 30.85,34.4 30.85,50.43 32.33,51.92 77.9,51.92 85.93,43.89 85.93,38 87.17,36.75 97.97,36.75 101.85,32.87 101.85,30.02 111,20.88 111,1.96 110.06,1.02 44.93,1.02 42.65,3.3 42.65,11.05 46.69,15.09 55.45,15.09 57.33,16.97 83.19,16.97 92.08,8.08 94.16,8.08 95.66,9.58 95.66,31.29 94.74,32.21 88.39,32.21 83.41,37.18
SOURCE on BOTTOM: 37.08,33.73 36.63,33.27 34.59,33.27 33.83,32.51 33.83,31.65 34.49,30.99 37.36,30.99 39.15,32.78 39.15,36.61 41.17,38.63 44.5,38.63 44.5,40.64 44.07,41.07 43.31,41.07 42.82,40.59 42.82,40.01 42.44,39.62 39.22,39.62 37.08,37.49
SOURCE on BOTTOM: 90.75,14.53 92.56,14.53 92.91,14.88 92.91,15.57 93.4,16.05 97.28,16.05 97.59,15.75 97.59,7.42 97.16,6.99 94.26,6.99 93.57,7.67 92.66,7.67 91.49,6.5 85.75,6.5 83.41,8.84 83.41,16.74 83.19,16.97 65.1,16.97 65.09,16.95 62.83,16.95 61.85,15.98 61.85,2.08 62.92,1.02 108.28,1.02 108.51,1.24 108.51,1.65 101.6,8.56 101.6,16.54 99.34,18.8 90.83,18.8 90.63,18.59 90.63,14.66
VDC AUX on BOTTOM: 57.4,42.72 56.41,42.72 56.34,42.8 56.34,46.71 57.89,48.26 66.9,48.26 67.34,47.83 67.34,47.27 66.98,46.91 57.91,46.91 57.48,46.48 57.48,42.8
VRECT on TOP: 40.61,20.65 44.27,20.65 45.09,19.84 45.09,16.33 44.37,15.62 43.31,15.62 40.28,18.64 40.28,20.32
VRECT on BOTTOM: 67.87,42.55 67.23,43.18 66.65,43.18 66.37,43.46 66.37,43.81 66.65,44.09 68.55,44.09 69.34,43.31 69.34,41.07 67.87,41.07
N11474110 on BOTTOM (solid shape): 30.61,17.38 30.61,15.26 29.87,14.52 28.4,14.52 27.61,15.31 27.61,16.88 27.61,16.88 27.61,17.38 28.11,17.88 28.61,17.38 29.11,17.88 29.61,17.38 30.11,17.88
N11474114 on BOTTOM (solid shape): 30.61,21.15 30.61,19.08 30.11,18.58 29.61,19.08 29.11,18.58 28.61,19.08 28.11,18.58 27.61,19.08 27.61,21.1 28.4,21.89 29.87,21.89
N11474236 on BOTTOM (solid shape): 22.99,17.38 22.99,15.26 22.25,14.52 20.78,14.52 19.99,15.31 19.99,16.88 19.99,16.88 19.99,17.38 20.49,17.88 20.99,17.38 21.49,17.88 21.99,17.38 22.49,17.88
N11474420 on BOTTOM (solid shape): 22.99,21.15 22.99,19.08 22.49,18.58 21.99,19.08 21.49,18.58 20.99,19.08 20.49,18.58 19.99,19.08 19.99,21.1 20.78,21.89 22.25,21.89
N11475153 on TOP: 50.06,47.17 49.66,47.57 37.41,47.57 36.91,47.07 36.91,43.41 49.83,43.41 50.06,43.64
N11475153 on TOP: 93.68,30.61 87.15,30.61 78.37,39.39 76.75,39.39 76.75,37.67 85.71,28.7 93.5,28.7 94.06,29.26 94.06,30.23
N11475153 on BOTTOM: 67.11,29.11 67.01,29.21 67.01,30.43 67.58,31 70.29,31 70.54,30.76 70.54,30.23 69.42,29.11
N11475153 on BOTTOM: 74.07,51.92 78.23,47.75 78.23,37.85 77.98,37.59 76.05,37.59 75.84,37.8 75.84,46.23 72.64,49.43 54.58,49.43 50.06,44.91 50.06,44.03 49.49,43.45 49.49,43.45 49.45,43.41 36.91,43.41 36.91,47.07 37.41,47.57 49.3,47.57 53.64,51.92
N11475153 on BOTTOM: 89.89,27.16 89.92,27.13 91.41,27.13 91.41,28.17 91.87,28.63 94.11,28.63 94.13,28.65 94.13,30.68 93.95,30.86 90.3,30.86 90.29,30.86 89.49,30.86 89.48,30.85 89.48,29.04 89.89,28.63
N11476179 on BOTTOM (solid shape): 48.59,30.56 44.79,30.56 44.79,32.81 42.99,32.81 42.99,35.51 44.64,35.51 44.64,37.46 44.74,37.46 45.66,37.84 46.04,38.76 46.04,38.86 48.59,38.86
N11476179 on TOP: 43.05,37.39 42.65,36.98 42.65,26.09 44.93,23.8 52.7,23.8 53.47,24.56 53.47,36.8 52.88,37.39
N11476179 on BOTTOM: 53,43.17 51.61,41.78 48.36,41.78 46.05,39.47 46.05,38.2 44.65,36.8 44.65,35.48 43.51,35.48 43.26,35.23 43.26,33.1 43.54,32.82 44.86,32.82 44.86,30.25 42.65,28.04 42.65,25.91 46.63,21.92 46.63,16.21 42.65,12.22 42.65,3.58 43.18,3.05 57.53,3.05 57.94,3.45 57.94,20.62 51.69,26.87 51.69,38.96 55.09,42.37 55.09,44.96 54.67,45.38 53.37,45.38 53,45.01
N11479125 on BOTTOM: 57.4,38.81 57.4,40.64 58.27,41.5 59.33,41.5 59.64,41.81 59.64,42.44 58.14,42.44 56.39,40.69 56.39,39.7 55.7,39.01 55.7,38.73 55.78,38.66 57.25,38.66
N11479237 on BOTTOM: 56.41,38.25 57.68,38.25 58.06,38.63 58.06,40.54 58.6,41.07 59.87,41.07 60.38,41.58 60.38,43.15 63.4,46.18 71.37,46.18 73.51,44.04 73.51,19.91 71.88,18.29 65.43,18.29 60.17,23.55 60.17,26.04 60.21,26.07 63.56,26.07 64.36,25.27 68.73,25.27 69.22,25.76 69.22,28.19 70.97,29.95 70.97,30.91 70.46,31.42 63.47,31.42 63.47,34.77 68.3,34.77 70.07,36.54 70.07,43.27 68.91,44.42 66.45,44.42 65.51,43.48 62.76,43.48 62.05,42.77 62.05,38.81 60.88,38.81 59.99,37.92 56.41,37.92 56.36,37.97 56.36,38.2
N11479555 on BOTTOM: 56.29,35.66 57.71,35.66 59.26,34.11 59.26,33.55 59.28,33.53 62.64,33.53 62.64,34.82 59.03,34.82 57.86,35.99 56.29,35.99 56.21,35.92 56.21,35.74
N11479611 on BOTTOM: 59.26,32.69 59.26,31.42 62.64,31.42 62.64,32.69
N11480864 on BOTTOM: 65.38,39.29 65.38,37.77 69.37,37.77 69.37,39.29
N11480868 on BOTTOM: 62.94,42.6 62.94,41.07 66.9,41.07 66.9,42.6
N11480902 on BOTTOM: 56.24,36.75 60.1,36.75 60.58,36.27 62.2,36.27 62.93,37 62.93,39.28 62.94,39.29 64.44,39.29 64.44,35.89 64.17,35.62 58.66,35.62 57.89,36.4 56.24,36.4 56.18,36.45 56.18,36.7
N11482311 on BOTTOM: 64.47,27.23 64.47,25.73 68.43,25.73 68.43,27.23
N11482333 on BOTTOM: 61.24,30.53 61.24,29.03 65.96,29.03 65.96,30.53
N11482355 on BOTTOM: 56.03,34.9 57.53,34.9 57.94,34.49 57.94,24.89 58.06,24.77 59.33,24.77 59.49,24.92 59.49,30.56 58.85,31.19 58.85,34.06 57.66,35.26 56.03,35.26 55.96,35.18 55.96,34.98
N11498787 on TOP: 140.47,29.45 132,20.98 127.89,20.98 127.23,21.64 127.23,25.37 129.9,28.04 132.38,28.04 136.54,32.19 136.54,39.2 137.01,39.67 138.3,39.67 140.47,37.5
N11498787 on BOTTOM: 117.47,21.58 117.47,22.91 118.95,24.38 126.24,24.38 129.9,28.04 132.38,28.04 136.55,32.21 136.55,39.19 137.03,39.67 138.33,39.67 141.99,36.02 141.99,24.18 141.38,23.57 130.56,23.57 125.4,18.42 118.38,18.42 118.38,18.42 118.38,20.34 118.72,20.68 126.21,20.68 128.35,22.81 128.35,22.91 128.24,23.01 128.12,23.01 126.09,20.98 118.08,20.98
N11498823 on BOTTOM: 148.36,41.71 142.44,41.71 141.94,41.2 141.94,38.1 142.44,37.59 148.06,37.59 149.02,38.56 149.02,41.05
N11498915 on BOTTOM: 141.88,43.36 142.39,42.85 149.08,42.85 149.1,42.87 149.1,46.9 148.43,47.57 142.19,47.57 141.88,47.26
N11498945 on BOTTOM: 84.05,30.45 84.05,28.93 85.29,28.93 86.59,27.64 86.59,27.1 88.11,27.1 88.11,28.63 88.62,29.13 88.62,30.86 84.45,30.86
N11499167 on TOP: 111.3,39.47 111.97,38.8 125.71,38.8 126.64,39.74 126.64,51.18 125.83,51.99 111.86,51.99 111.3,51.44
N11499167 on BOTTOM: 117.2,29.51 117.2,46.13 118.95,47.88 124.26,47.88 124.59,47.55 124.59,44.7 125.25,44.04 125.93,44.04 126.64,43.33 126.64,34 121.28,28.64 118.07,28.64
N11499175 on BOTTOM: 126.21,46.28 126.21,44.78 130.23,44.78 130.23,46.28
N11499225 on BOTTOM: 94.46,21.89 93.56,21 92.68,21 90.91,22.77 90.91,26.06 90.91,26.06 93.43,26.06 93.43,23.84 93.41,23.83 93.41,23.17 93.68,22.91 96.37,22.91 96.95,22.32 96.95,21.97 96.88,21.89
N11499609 on BOTTOM: 108.79,17.4 109.98,17.4 110.27,17.11 110.27,10.48 110.59,10.16 112.04,10.16 112.33,10.45 112.33,15.61 110.16,17.78 108.79,17.78 108.74,17.73 108.74,17.45
N11499655 on BOTTOM: 108.74,20.02 110.97,20.02 111.53,20.57 112.73,20.57 112.88,20.42 112.88,19.33 112.7,19.15 111.51,19.15 111,19.66 108.71,19.66 108.64,19.74 108.64,19.91
N11939314 on BOTTOM: 60.2,28.19 60.2,26.92 63.55,26.92 63.55,28.19
N11966145 on BOTTOM: 93.83,10.92 93.83,10.19 93.46,9.82 90.57,9.82 90.57,11.34 90.58,11.34 93.41,11.34
N11995900 on BOTTOM: 58.27,46.2 58.27,44.06 58.76,43.56 59.96,43.56 61.8,45.4 61.8,46.54 58.6,46.54
N12000412 on BOTTOM: 65.02,36.91 65.02,35.64 68.38,35.64 68.38,36.91
N12033400 on BOTTOM: 128.83,17.7 129.59,18.47 132.63,18.47 133.41,17.68 134.85,17.68 134.85,17.68 134.85,18.55 134.35,19.04 133.17,19.04 132.82,19.39 132.82,20.66 132.82,20.66 130.46,20.66 127.91,18.11 127.91,15.34 127.05,14.48 122.56,14.48 122.22,14.15 122.22,12.85 123.88,11.2 123.88,11.2 123.97,11.1 123.97,10.49 123.97,10.39 124.84,10.39 124.84,10.39 124.84,11.21 123.88,12.17 123.88,13.08 124.16,13.36 128.32,13.36 128.83,13.87
N12033400 on BOTTOM: 145.36,28.68 145.36,33.25 145.2,33.41 143.97,33.41 143.97,30.05 143.28,29.36 143.28,28.83 143.51,28.6 145.29,28.6
N12033444 on BOTTOM: 148.07,32.38 149.09,32.38 149.09,32.41 149.09,33.25 148.1,33.25 147.95,33.41 146.31,33.41 146.3,33.41 146.09,33.41 146.09,32.15 146.1,32.14 147.83,32.14
N12033508 on BOTTOM: 150.24,25.22 150.24,29.03 148.95,30.33 148.47,30.33 147.75,29.62 146.48,29.62 146.48,30.48 147.39,31.39 149.12,31.39 151.13,29.39 151.13,25.2 150.98,25.04 150.42,25.04
N12033698 on BOTTOM: 138.55,14.83 138.86,15.14 140.31,15.14 140.31,15.75 138.58,15.75 137.34,14.5 137.34,14.48 137.29,14.43 137.29,11.7 137.29,11.7 138.55,11.7
N12033710 on BOTTOM: 142.72,9.45 141.78,9.45 141.5,9.73 141.5,13.51 141.21,13.81 141.21,15.02 141.26,15.08 142.58,15.08 144.9,17.4 147.01,17.4 147.01,15.87 144.68,15.87 142.9,14.1 142.9,9.63
N12033758 on BOTTOM: 138.93,21.75 138.93,23.01 138.92,23.01 137.59,23.01 137.25,22.67 136.41,22.67 136.41,22.67 136.13,22.67 136.13,22.67 136.13,21.4 138.57,21.4
N12033762 on BOTTOM: 140.31,17.68 138.84,17.68 137.67,18.85 137.67,20.8 137.67,20.8 137.67,20.88 137.68,20.88 138.92,20.88 140,21.96 141.43,21.96 141.43,20.4 140.31,19.28
N12033774 on BOTTOM: 138.86,17.02 140.67,17.02 141.17,17.53 141.17,19.49 141.18,19.49 142.47,19.49 142.47,15.94 142.47,15.94 141.18,15.94 140.71,16.41 138.86,16.41
N12033856 on BOTTOM: 143.78,12.25 143.31,12.73 143.31,13.82 144.64,15.15 145.92,15.15 145.92,15.15 145.92,13.88 145.26,13.22 145.26,12.35 145.26,12.25 145.26,12.25
N12033856 on BOTTOM: 136.25,19.62 136.25,20.42 136.01,20.66 133.68,20.66 133.68,19.39 133.68,19.39 136.01,19.39
N12033928 on BOTTOM: 144.58,21.96 144.58,18.23 143.31,18.23 143.31,18.23 143.31,21.95 143.31,21.96
N12034090 on BOTTOM: 134.85,15.75 129.59,15.75 129.49,15.65 129.49,12.22 129.5,12.22 130.48,12.22 133.4,15.14 134.85,15.14
N12034098 on BOTTOM: 135.25,17.02 133.4,17.02 132.65,17.77 129.5,17.77 129.5,16.5 129.59,16.41 134.95,16.41 135.18,16.18 135.18,12.09 135.18,12.08 135.18,11.71 135.19,11.69 136.42,11.69 136.42,15.85
N12052159 on BOTTOM: 117.85,12.12 119.55,12.12 120.06,11.61 121.03,11.61 122.1,10.54 122.1,10.39 122.96,10.39 122.96,11.24 121.02,13.18 116.54,13.18 116.53,13.18 116.37,13.18 115.35,12.16 115.35,11.01 116.74,11.01
N12053445 on BOTTOM: 89.12,23.78 89.12,26.07 89.11,26.07 86.64,26.07 85.56,27.15 84.05,27.15 84.05,25.63 85.87,23.81
N12080403 on BOTTOM: 129.11,11.71 129.02,11.62 127.55,11.62 127.41,11.76 127.41,12.8 127.48,12.88 128.6,12.88 129.11,12.37

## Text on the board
Ref Des/Silkscreen Bottom: TM | A | LYTSwitch -6
Ref Des/Silkscreen Top: L | N | 2032 | S/N | DER-920 Rev A | DIM- | RTN | VOUT | DIM+
User.6: 3 SLOTS | DELETE THESE HOLES: | 1.  THROUGH HOLES ARE PLATED THROUGH. | EXCEPTIONS WILL BE NOTED IN DRILL CHART "NOTE". | 2.  MATERIAL: BASE MATERIAL LAMINATED EPOXY | UL APPROVED MANUFACTURED SOURCE FOR FR4. | 3.  SOLDER PLATE WILL BE RoHS COMPLIANT. | 4.  SOLDER MASK LPI (LIQUID PHOTO IMAGEABLE) BOTH SIDES. COLOR GREEN. | SOLDER MASK (REGISTRATION) -0/+0.003" | 5.  SILKSCREEN TOP/BOTTOM SIDE. COLOR WHITE. (MIN.WIDTH 0.005" MAX.WIDTH 0.010") | 6.  FINISH TO BE SMOBC. | 7.  ENIG OR RoHS COMPLIANT. | 8.  BOARD DIMENSION +/- 0.005" | 9.  DRILL TOLERANCE +/- 0.003" | 10. TRACE WIDTH UNDER 0.010" +/- 0.002" | TRACE WIDTH OVER 0.011" +/- 0.005" | 11. TRACE SPACE +/- 0.003" | 12. MATERIAL FR4 COPPER 2 OZ BOARD THICKNESS 0.062" | NOTES: UNLESS OTHERWISE SPECIFIED
User.9: FIGURE | FINISHED_SIZE | 20.0 | 30.0 | 40.0 | 46.0 | 50.0 | 52.0 | 55.0 | 60.0 | DRILL CHART: TOP to BOTTOM | ALL UNITS ARE IN MILS | TOLERANCE_DRILL | +3.0/-3.0 | PLATED | QTY | 310 | 12 | 24 | 2 | 4 | 8 | 3
